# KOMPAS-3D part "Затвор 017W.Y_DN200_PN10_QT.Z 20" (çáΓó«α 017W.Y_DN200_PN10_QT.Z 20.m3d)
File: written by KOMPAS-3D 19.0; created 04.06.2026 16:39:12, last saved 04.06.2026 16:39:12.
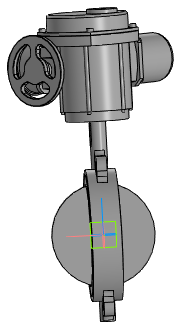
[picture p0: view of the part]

Document properties: Автор: Энергия; Полное имя файла: ..\..\..\3d для проектировщиков\017W разные\x.x Тип 017W.Y(S) Затвор дисковый поворотный межфланцевый\Затвор 017W.Y(S)_DN32-DN450_QT.Z\Затвор 017W.Y_DN200_PN10_QT.Z 20.a3d

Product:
- Part/product: Затвор 017W.Y_DN200_PN10_QT.Z 20
    Масса: 57.929

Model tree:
1. Операция без истории:1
